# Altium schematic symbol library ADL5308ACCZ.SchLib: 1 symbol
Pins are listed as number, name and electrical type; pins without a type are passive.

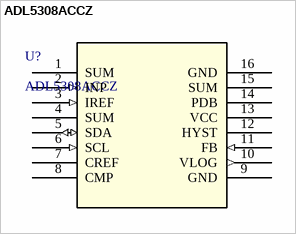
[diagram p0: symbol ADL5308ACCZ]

## ADL5308ACCZ
designator U?
Fast Response 188 dB Range (10 pA to 25 mA) Logarithmic Converter; Manufacturer_Name: Analog Devices Inc
footprint CC-14-4_ADI
pins: 1 SUM, 2 INP (in), 3 IREF (in), 4 SUM, 5 SDA (io), 6 SCL (in), 7 CREF (power), 8 CMP (power), 9 GND (power), 10 VLOG (out), 11 FB (in), 12 HYST, 13 VCC (power), 14 PDB (power), 15 SUM, 16 GND (power)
